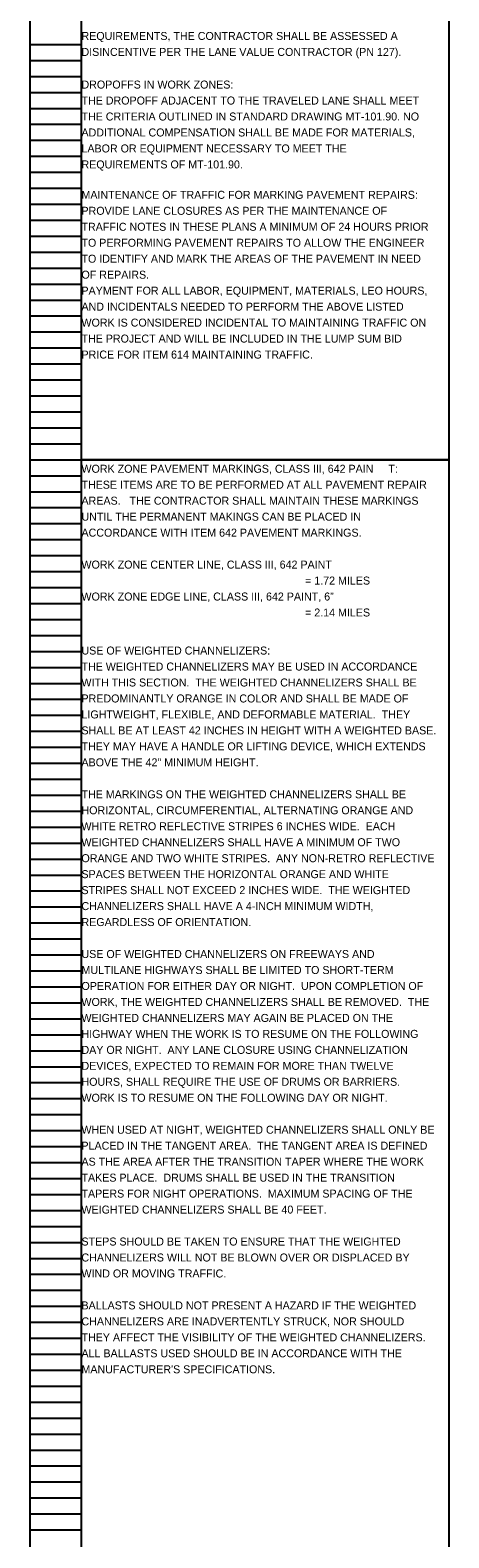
# Model space of a CAD drawing. Extents: x 16463 to 16500, y 5400 to 5823.
# Drawn here: x 16463.05 to 16470.39, y 5744.09 to 5770.52 of the extents above; entities that cross this region are included whole.
import ezdxf

# ---------------------------------------------------------------- set-up
doc = ezdxf.new("R2010")
doc.units = 0
for name, color, linetype in [('Default', 7, 'Continuous'), ('SC_Scratch1', 7, 'Continuous'), ('SH_Data', 7, 'Continuous')]:
    doc.layers.add(name, color=color, linetype=linetype)

msp = doc.modelspace()

# ---------------------------------------------------------------- linework, layer by layer
at = {"layer": 'SC_Scratch1'}
for points in [[(16463.949, 5783.152), (16470.389, 5783.152), (16470.389, 5762.992), (16463.949, 5762.992)], [(16463.949, 5762.992), (16470.389, 5762.992), (16470.389, 5742.832), (16463.949, 5742.832)]]:
    msp.add_lwpolyline(points, close=True, dxfattribs=at)
at = {"layer": 'SH_Data'}
for p, q in [((16463.049, 5762.992), (16463.049, 5783.152)), ((16463.949, 5762.992), (16463.949, 5783.152)), ((16463.049, 5770.272), (16463.949, 5770.272)), ((16463.049, 5769.992), (16463.949, 5769.992)), ((16463.049, 5769.712), (16463.949, 5769.712)), ((16463.049, 5769.432), (16463.949, 5769.432)), ((16463.049, 5769.152), (16463.949, 5769.152)), ((16463.049, 5768.872), (16463.949, 5768.872)), ((16463.049, 5768.592), (16463.949, 5768.592)), ((16463.049, 5768.312), (16463.949, 5768.312)), ((16463.049, 5768.032), (16463.949, 5768.032)), ((16463.049, 5767.752), (16463.949, 5767.752)), ((16463.049, 5767.472), (16463.949, 5767.472)), ((16463.049, 5767.192), (16463.949, 5767.192)), ((16463.049, 5766.912), (16463.949, 5766.912)), ((16463.049, 5766.632), (16463.949, 5766.632)), ((16463.049, 5766.352), (16463.949, 5766.352)), ((16463.049, 5766.072), (16463.949, 5766.072)), ((16463.049, 5765.792), (16463.949, 5765.792)), ((16463.049, 5765.512), (16463.949, 5765.512)), ((16463.049, 5765.232), (16463.949, 5765.232)), ((16463.049, 5764.952), (16463.949, 5764.952)), ((16463.049, 5764.672), (16463.949, 5764.672)), ((16463.049, 5764.392), (16463.949, 5764.392)), ((16463.049, 5764.112), (16463.949, 5764.112)), ((16463.049, 5763.832), (16463.949, 5763.832)), ((16463.049, 5763.552), (16463.949, 5763.552)), ((16463.049, 5763.272), (16463.949, 5763.272)), ((16463.049, 5742.832), (16463.049, 5762.992)), ((16463.049, 5762.992), (16463.949, 5762.992)), ((16463.049, 5762.992), (16463.949, 5762.992)), ((16463.949, 5742.832), (16463.949, 5762.992)), ((16463.049, 5762.712), (16463.949, 5762.712)), ((16463.049, 5762.432), (16463.949, 5762.432)), ((16463.049, 5762.152), (16463.949, 5762.152)), ((16463.049, 5761.872), (16463.949, 5761.872)), ((16463.049, 5761.592), (16463.949, 5761.592)), ((16463.049, 5761.312), (16463.949, 5761.312)), ((16463.049, 5761.032), (16463.949, 5761.032)), ((16463.049, 5760.752), (16463.949, 5760.752)), ((16463.049, 5760.472), (16463.949, 5760.472)), ((16463.049, 5760.192), (16463.949, 5760.192)), ((16463.049, 5759.912), (16463.949, 5759.912)), ((16463.049, 5759.632), (16463.949, 5759.632)), ((16463.049, 5759.352), (16463.949, 5759.352)), ((16463.049, 5759.072), (16463.949, 5759.072)), ((16463.049, 5758.792), (16463.949, 5758.792)), ((16463.049, 5758.512), (16463.949, 5758.512)), ((16463.049, 5758.232), (16463.949, 5758.232)), ((16463.049, 5757.952), (16463.949, 5757.952)), ((16463.049, 5757.672), (16463.949, 5757.672)), ((16463.049, 5757.392), (16463.949, 5757.392)), ((16463.049, 5757.112), (16463.949, 5757.112)), ((16463.049, 5756.832), (16463.949, 5756.832)), ((16463.049, 5756.552), (16463.949, 5756.552)), ((16463.049, 5756.272), (16463.949, 5756.272)), ((16463.049, 5755.992), (16463.949, 5755.992)), ((16463.049, 5755.712), (16463.949, 5755.712)), ((16463.049, 5755.432), (16463.949, 5755.432)), ((16463.049, 5755.152), (16463.949, 5755.152)), ((16463.049, 5754.872), (16463.949, 5754.872)), ((16463.049, 5754.592), (16463.949, 5754.592)), ((16463.049, 5754.312), (16463.949, 5754.312)), ((16463.049, 5754.032), (16463.949, 5754.032)), ((16463.049, 5753.752), (16463.949, 5753.752)), ((16463.049, 5753.472), (16463.949, 5753.472)), ((16463.049, 5753.192), (16463.949, 5753.192)), ((16463.049, 5752.912), (16463.949, 5752.912)), ((16463.049, 5752.632), (16463.949, 5752.632)), ((16463.049, 5752.352), (16463.949, 5752.352)), ((16463.049, 5752.072), (16463.949, 5752.072)), ((16463.049, 5751.792), (16463.949, 5751.792)), ((16463.049, 5751.512), (16463.949, 5751.512)), ((16463.049, 5751.232), (16463.949, 5751.232)), ((16463.049, 5750.952), (16463.949, 5750.952)), ((16463.049, 5750.672), (16463.949, 5750.672)), ((16463.049, 5750.392), (16463.949, 5750.392)), ((16463.049, 5750.112), (16463.949, 5750.112)), ((16463.049, 5749.832), (16463.949, 5749.832)), ((16463.049, 5749.552), (16463.949, 5749.552)), ((16463.049, 5749.272), (16463.949, 5749.272)), ((16463.049, 5748.992), (16463.949, 5748.992)), ((16463.049, 5748.712), (16463.949, 5748.712)), ((16463.049, 5748.432), (16463.949, 5748.432)), ((16463.049, 5748.152), (16463.949, 5748.152)), ((16463.049, 5747.872), (16463.949, 5747.872)), ((16463.049, 5747.592), (16463.949, 5747.592)), ((16463.049, 5747.312), (16463.949, 5747.312)), ((16463.049, 5747.032), (16463.949, 5747.032)), ((16463.049, 5746.752), (16463.949, 5746.752)), ((16463.049, 5746.472), (16463.949, 5746.472)), ((16463.049, 5746.192), (16463.949, 5746.192)), ((16463.049, 5745.912), (16463.949, 5745.912)), ((16463.049, 5745.632), (16463.949, 5745.632)), ((16463.049, 5745.352), (16463.949, 5745.352)), ((16463.049, 5745.072), (16463.949, 5745.072)), ((16463.049, 5744.792), (16463.949, 5744.792)), ((16463.049, 5744.512), (16463.949, 5744.512)), ((16463.049, 5744.232), (16463.949, 5744.232))]:
    msp.add_line(p, q, dxfattribs=at)

# ---------------------------------------------------------------- texts
at = {"layer": 'Default'}
for s, p in [('REQUIREMENTS, THE CONTRACTOR SHALL BE ASSESSED A ', (16463.949, 5770.351)), ('DISINCENTIVE PER THE LANE VALUE CONTRACTOR (PN 127).', (16463.949, 5770.071)), ('DROPOFFS IN WORK ZONES:', (16463.949, 5769.499)), ('THE DROPOFF ADJACENT TO THE TRAVELED LANE SHALL MEET ', (16463.949, 5769.219)), ('THE CRITERIA OUTLINED IN STANDARD DRAWING MT-101.90. NO ', (16463.949, 5768.939)), ('ADDITIONAL COMPENSATION SHALL BE MADE FOR MATERIALS, ', (16463.949, 5768.659)), ('LABOR OR EQUIPMENT NECESSARY TO MEET THE ', (16463.949, 5768.379)), ('REQUIREMENTS OF MT-101.90.', (16463.949, 5768.099)), ('MAINTENANCE OF TRAFFIC FOR MARKING PAVEMENT REPAIRS:', (16463.949, 5767.566)), ('PROVIDE LANE CLOSURES AS PER THE MAINTENANCE OF ', (16463.949, 5767.286)), ('TRAFFIC NOTES IN THESE PLANS A MINIMUM OF 24 HOURS PRIOR ', (16463.949, 5767.006)), ('TO PERFORMING PAVEMENT REPAIRS TO ALLOW THE ENGINEER ', (16463.949, 5766.726)), ('TO IDENTIFY AND MARK THE AREAS OF THE PAVEMENT IN NEED ', (16463.949, 5766.446)), ('OF REPAIRS.', (16463.949, 5766.166)), ('PAYMENT FOR ALL LABOR, EQUIPMENT, MATERIALS, LEO HOURS, ', (16463.949, 5765.886)), ('AND INCIDENTALS NEEDED TO PERFORM THE ABOVE LISTED ', (16463.949, 5765.606)), ('WORK IS CONSIDERED INCIDENTAL TO MAINTAINING TRAFFIC ON ', (16463.949, 5765.326)), ('THE PROJECT AND WILL BE INCLUDED IN THE LUMP SUM BID ', (16463.949, 5765.046)), ('PRICE FOR ITEM 614 MAINTAINING TRAFFIC.', (16463.949, 5764.766)), ('WORK ZONE PAVEMENT MARKINGS, CLASS III, 642 PAIN', (16463.949, 5762.764)), ('T:', (16469.329, 5762.764)), ('THESE ITEMS ARE TO BE PERFORMED AT ALL PAVEMENT REPAIR ', (16463.949, 5762.484)), ('AREAS.   THE CONTRACTOR SHALL MAINTAIN THESE MARKINGS ', (16463.949, 5762.204)), ('UNTIL THE PERMANENT MAKINGS CAN BE PLACED IN ', (16463.949, 5761.924)), ('ACCORDANCE WITH ITEM 642 PAVEMENT MARKINGS. ', (16463.949, 5761.644)), ('WORK ZONE CENTER LINE, CLASS III, 642 PAINT  ', (16463.949, 5761.084)), ('= 1.72 MILES', (16467.869, 5760.804)), ('WORK ZONE EDGE LINE, CLASS III, 642 PAINT, 6”', (16463.949, 5760.524)), ('= 2.14 MILES', (16467.869, 5760.244)), ('USE OF WEIGHTED CHANNELIZERS:', (16463.949, 5759.577)), ('THE WEIGHTED CHANNELIZERS MAY BE USED IN ACCORDANCE ', (16463.949, 5759.297)), ('WITH THIS SECTION.  THE WEIGHTED CHANNELIZERS SHALL BE ', (16463.949, 5759.017)), ('PREDOMINANTLY ORANGE IN COLOR AND SHALL BE MADE OF ', (16463.949, 5758.737)), ('LIGHTWEIGHT, FLEXIBLE, AND DEFORMABLE MATERIAL.  THEY ', (16463.949, 5758.457)), ('SHALL BE AT LEAST 42 INCHES IN HEIGHT WITH A WEIGHTED BASE.  ', (16463.949, 5758.177)), ('THEY MAY HAVE A HANDLE OR LIFTING DEVICE, WHICH EXTENDS ', (16463.949, 5757.897)), ('ABOVE THE 42" MINIMUM HEIGHT.', (16463.949, 5757.617)), ('THE MARKINGS ON THE WEIGHTED CHANNELIZERS SHALL BE ', (16463.949, 5757.057)), ('HORIZONTAL, CIRCUMFERENTIAL, ALTERNATING ORANGE AND ', (16463.949, 5756.777)), ('WHITE RETRO REFLECTIVE STRIPES 6 INCHES WIDE.  EACH ', (16463.949, 5756.497)), ('WEIGHTED CHANNELIZERS SHALL HAVE A MINIMUM OF TWO ', (16463.949, 5756.217)), ('ORANGE AND TWO WHITE STRIPES.  ANY NON-RETRO REFLECTIVE ', (16463.949, 5755.937)), ('SPACES BETWEEN THE HORIZONTAL ORANGE AND WHITE ', (16463.949, 5755.657)), ('STRIPES SHALL NOT EXCEED 2 INCHES WIDE.  THE WEIGHTED ', (16463.949, 5755.377)), ('CHANNELIZERS SHALL HAVE A 4-INCH MINIMUM WIDTH, ', (16463.949, 5755.097)), ('REGARDLESS OF ORIENTATION.', (16463.949, 5754.817)), ('USE OF WEIGHTED CHANNELIZERS ON FREEWAYS AND ', (16463.949, 5754.257)), ('MULTILANE HIGHWAYS SHALL BE LIMITED TO SHORT-TERM ', (16463.949, 5753.977)), ('OPERATION FOR EITHER DAY OR NIGHT.  UPON COMPLETION OF ', (16463.949, 5753.697)), ('WORK, THE WEIGHTED CHANNELIZERS SHALL BE REMOVED.  THE ', (16463.949, 5753.417)), ('WEIGHTED CHANNELIZERS MAY AGAIN BE PLACED ON THE ', (16463.949, 5753.137)), ('HIGHWAY WHEN THE WORK IS TO RESUME ON THE FOLLOWING ', (16463.949, 5752.857)), ('DAY OR NIGHT.  ANY LANE CLOSURE USING CHANNELIZATION ', (16463.949, 5752.577)), ('DEVICES, EXPECTED TO REMAIN FOR MORE THAN TWELVE ', (16463.949, 5752.297)), ('HOURS, SHALL REQUIRE THE USE OF DRUMS OR BARRIERS.  ', (16463.949, 5752.017)), ('WORK IS TO RESUME ON THE FOLLOWING DAY OR NIGHT.', (16463.949, 5751.737)), ('WHEN USED AT NIGHT, WEIGHTED CHANNELIZERS SHALL ONLY BE ', (16463.949, 5751.177)), ('PLACED IN THE TANGENT AREA.  THE TANGENT AREA IS DEFINED ', (16463.949, 5750.897)), ('AS THE AREA AFTER THE TRANSITION TAPER WHERE THE WORK ', (16463.949, 5750.617)), ('TAKES PLACE.  DRUMS SHALL BE USED IN THE TRANSITION ', (16463.949, 5750.337)), ('TAPERS FOR NIGHT OPERATIONS.  MAXIMUM SPACING OF THE ', (16463.949, 5750.057)), ('WEIGHTED CHANNELIZERS SHALL BE 40 FEET.', (16463.949, 5749.777)), ('STEPS SHOULD BE TAKEN TO ENSURE THAT THE WEIGHTED ', (16463.949, 5749.217)), ('CHANNELIZERS WILL NOT BE BLOWN OVER OR DISPLACED BY ', (16463.949, 5748.937)), ('WIND OR MOVING TRAFFIC.  ', (16463.949, 5748.657)), ('BALLASTS SHOULD NOT PRESENT A HAZARD IF THE WEIGHTED ', (16463.949, 5748.097)), ('CHANNELIZERS ARE INADVERTENTLY STRUCK, NOR SHOULD ', (16463.949, 5747.817)), ('THEY AFFECT THE VISIBILITY OF THE WEIGHTED CHANNELIZERS.  ', (16463.949, 5747.537)), ('ALL BALLASTS USED SHOULD BE IN ACCORDANCE WITH THE ', (16463.949, 5747.257)), ("MANUFACTURER'S SPECIFICATIONS.", (16463.949, 5746.977))]:
    msp.add_text(s, height=0.14, dxfattribs=at).set_placement(p)

doc.saveas('drawing.dxf')
